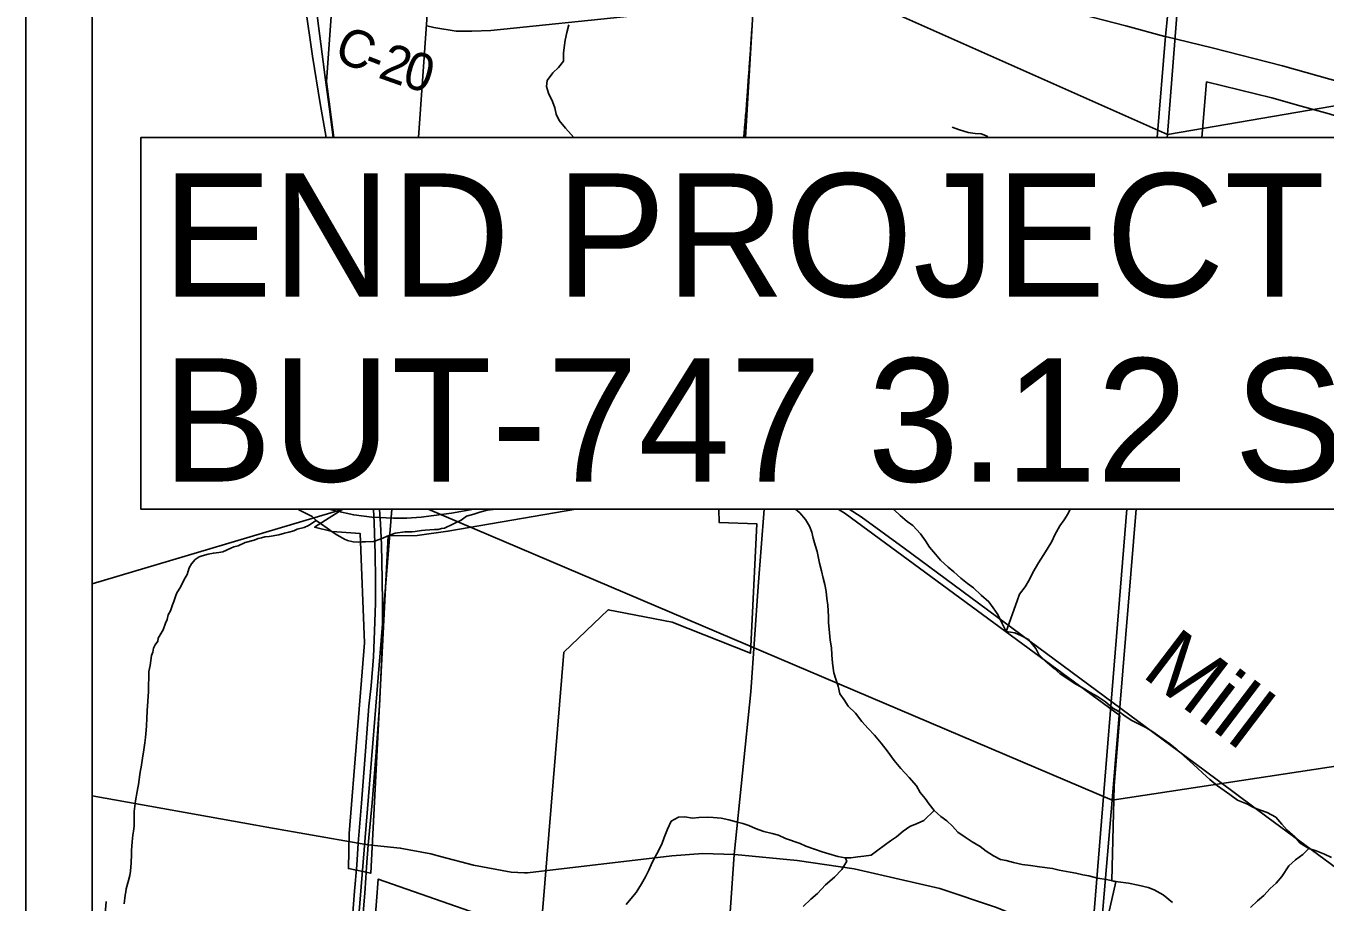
# Model space of a CAD drawing. Extents: x 0 to 34, y 0 to 22.
# Drawn here: x 2 to 3.964, y 18.207 to 19.532 of the extents above; entities that cross this region are included whole.
import ezdxf

# ---------------------------------------------------------------- set-up
doc = ezdxf.new("R2010")
doc.units = 0
for name, color, linetype in [('Default', 7, 'Continuous'), ('GM_X_City_Street', 7, 'Continuous'), ('GM_X_County_Road', 7, 'Continuous'), ('GM_X_County_Road_Text', 7, 'Continuous'), ('GM_X_Minor_River', 7, 'Continuous'), ('GM_X_Minor_River_Text', 7, 'Continuous'), ('GM_X_Rail_Line', 7, 'Continuous'), ('GM_X_Section', 7, 'Continuous'), ('GM_X_State_Route', 7, 'Continuous'), ('GM_X_Township_Road', 7, 'Continuous'), ('SH_Cut_Line', 7, 'Continuous'), ('SH_Data', 7, 'Continuous'), ('SH_Text', 7, 'Continuous')]:
    doc.layers.add(name, color=color, linetype=linetype)

msp = doc.modelspace()

# ---------------------------------------------------------------- linework, layer by layer
at = {"layer": 'Default'}
for points in [[(2.4657, 19.3633), (2.4543, 19.4479), (2.4643, 19.5889), (2.2326, 19.6977), (2.2384, 19.7007), (2.2301, 19.7049), (2.2689, 19.7927), (2.2692, 19.8013), (2.2689, 19.8136), (2.2677, 19.8229), (2.2505, 19.9535), (2.2526, 19.9723), (2.2744, 20.0988), (2.3397, 20.0939), (2.3259, 20.1979), (2.313, 20.2941), (2.2914, 20.4608), (2.2761, 20.579), (2.2821, 20.6918), (2.2391, 20.7041), (2.238, 20.7101), (2.1, 20.7213), (2.1, 19.3633)], [(2.5933, 19.3633), (2.6281, 19.856), (2.1, 19.6477), (2.1, 19.3633)], [(2.4643, 19.5889), (2.4543, 19.4479), (2.4657, 19.3633)], [(3.0852, 19.3633), (3.0855, 19.3657), (3.0858, 19.3691), (3.086, 19.3719), (3.0863, 19.3748), (3.0866, 19.3785), (3.087, 19.3827), (3.0873, 19.3864), (3.0876, 19.3898), (3.0879, 19.3932), (3.0881, 19.3963), (3.0884, 19.3997), (3.0887, 19.4031), (3.0889, 19.4053), (3.0891, 19.4076), (3.0893, 19.4104), (3.0894, 19.4127), (3.0896, 19.415), (3.0898, 19.4181), (3.09, 19.4212), (3.0902, 19.4246), (3.0905, 19.428), (3.0907, 19.4311), (3.091, 19.4351), (3.0913, 19.4388), (3.0914, 19.441), (3.0916, 19.4433), (3.0918, 19.4464), (3.0921, 19.4504), (3.0924, 19.4541), (3.0926, 19.4566), (3.0928, 19.4594), (3.093, 19.4626), (3.0932, 19.4654), (3.0934, 19.4679), (3.0936, 19.4708), (3.0938, 19.4745), (3.0941, 19.4776), (3.0943, 19.4807), (3.0946, 19.4847), (3.0948, 19.4878), (3.095, 19.4906), (3.0952, 19.4937), (3.0954, 19.496), (3.0955, 19.4985), (3.0958, 19.502), (3.096, 19.5059), (3.0963, 19.5105), (3.0966, 19.5141), (3.0968, 19.5167), (3.097, 19.5192), (3.0972, 19.5221), (3.0974, 19.5246), (3.0976, 19.5272), (3.0979, 19.5308), (3.0982, 19.5342)], [(2.1, 18.801), (2.1, 18.6881), (2.4795, 18.801)], [(2.4795, 18.801), (2.1, 18.6881), (2.1, 17.6666), (2.4678, 17.7524), (2.5533, 18.801)], [(2.1, 18.801), (2.1, 17.6674), (2.4362, 17.7466), (2.4945, 17.7428), (2.5327, 18.2417), (2.7778, 18.1558), (2.8131, 18.5849), (2.8804, 18.6491), (2.977, 18.6303), (3.0953, 18.5833), (3.1049, 18.7791), (3.0479, 18.7812), (3.0475, 18.801)], [(2.4792, 18.801), (2.4364, 18.7739), (2.4628, 18.7673), (2.5055, 18.7642), (2.512, 18.5991), (2.4887, 18.3107), (2.4876, 18.2576), (2.5212, 18.2506), (2.5475, 18.7608), (2.5913, 18.7614), (2.6379, 18.7677), (2.8315, 18.801)], [(2.8315, 18.801), (2.6379, 18.7677), (2.5913, 18.7614), (2.5475, 18.7608), (2.5212, 18.2506), (2.4876, 18.2576), (2.4887, 18.3107), (2.512, 18.5991), (2.5055, 18.7642), (2.4628, 18.7673), (2.4364, 18.7739), (2.4792, 18.801)], [(3.0475, 18.801), (3.0479, 18.7812), (3.1049, 18.7791), (3.0953, 18.5833), (2.977, 18.6303), (2.8804, 18.6491), (2.8131, 18.5849), (2.7778, 18.1558), (2.5327, 18.2417), (2.4945, 17.7428)], [(3.6366, 18.1888), (3.6479, 18.2377), (3.642, 18.2391), (3.6451, 18.3827), (3.654, 18.4891), (3.2387, 18.7947), (3.2282, 18.801)]]:
    msp.add_lwpolyline(points, dxfattribs=at)
at = {"layer": 'GM_X_City_Street'}
msp.add_line((3.0881, 19.3633), (3.1002, 19.5668), dxfattribs=at)
msp.add_lwpolyline([(2.8276, 16.5443), (2.8934, 16.7739), (2.923, 16.8761), (2.9901, 17.1121), (3.006, 17.1613), (3.0262, 17.5439), (3.0263, 17.5466), (3.0267, 17.5529), (3.0555, 18.0608), (3.0708, 18.2789), (3.0961, 18.5247), (3.1069, 18.6844), (3.1163, 18.801)], dxfattribs=at)
at = {"layer": 'GM_X_County_Road'}
for p, q in [((2.3643, 18.3202), (2.5025, 18.2962)), ((2.5025, 18.2962), (2.5176, 18.2936))]:
    msp.add_line(p, q, dxfattribs=at)
for points in [[(3.1999, 19.5773), (3.2602, 19.5828), (3.3439, 19.5909), (3.4073, 19.5947), (3.4619, 19.5839), (3.5807, 19.5533), (3.663, 19.5321), (3.722, 19.5159)], [(2.6061, 19.5319), (2.6167, 19.5295), (2.6506, 19.5239), (2.6743, 19.5237), (2.703, 19.5246), (2.918, 19.5471), (3.06, 19.5636), (3.1002, 19.5668)], [(3.722, 19.5159), (3.723, 19.5156), (3.7934, 19.4984), (3.9, 19.4714), (4.0267, 19.4358), (4.0449, 19.4335), (4.0688, 19.4339), (4.1158, 19.4408), (4.3754, 19.4815), (4.5038, 19.5025), (4.601, 19.5196), (4.6497, 19.5297), (4.6684, 19.5314)], [(2.1, 18.3678), (2.3476, 18.3232), (2.3643, 18.3202)], [(2.5176, 18.2936), (2.5659, 18.2886), (2.612, 18.28), (2.6265, 18.2762)], [(2.6265, 18.2762), (2.6768, 18.2629), (2.7335, 18.2524), (2.7535, 18.2513)], [(2.7535, 18.2513), (2.7585, 18.2511), (2.9767, 18.2769), (3.0232, 18.2806), (3.0708, 18.2789), (3.0718, 18.2788)], [(3.0718, 18.2788), (3.1658, 18.2699), (3.2524, 18.2573), (3.3817, 18.2277), (3.4672, 18.1987), (3.5902, 18.1482), (3.6107, 18.1365), (3.6157, 18.1336), (3.627, 18.1271)]]:
    msp.add_lwpolyline(points, dxfattribs=at)
at = {"layer": 'GM_X_Minor_River'}
for points in [[(2.815, 19.5103), (2.8176, 19.5216), (2.8206, 19.5333)], [(2.8282, 19.3633), (2.8241, 19.3674), (2.8156, 19.3772), (2.8061, 19.3889), (2.8018, 19.3981), (2.7998, 19.4077), (2.7959, 19.4177), (2.7902, 19.4301), (2.7871, 19.4404), (2.7881, 19.4495), (2.7964, 19.461), (2.8054, 19.4691), (2.8125, 19.4784), (2.8129, 19.4906), (2.8135, 19.4993), (2.815, 19.5103)], [(3.4555, 19.3633), (3.4531, 19.3649), (3.4444, 19.3686), (3.4349, 19.3693), (3.4243, 19.3708), (3.41, 19.375), (3.4003, 19.3787)], [(2.6329, 18.7722), (2.6283, 18.772), (2.623, 18.7706), (2.6176, 18.7703), (2.6108, 18.7701), (2.6035, 18.7696), (2.5982, 18.7689), (2.5882, 18.7673), (2.5837, 18.767), (2.573, 18.7669), (2.5581, 18.7646), (2.5485, 18.7615), (2.537, 18.7564), (2.5255, 18.7522), (2.5133, 18.7517), (2.5083, 18.7515), (2.5034, 18.7512), (2.4946, 18.7518), (2.4859, 18.7539), (2.4814, 18.756), (2.4747, 18.7596), (2.4698, 18.7623), (2.4646, 18.7659), (2.4552, 18.7722), (2.4466, 18.7782), (2.4388, 18.7841), (2.4329, 18.7899), (2.4235, 18.7947), (2.4156, 18.7987), (2.4108, 18.801)], [(2.7172, 18.801), (2.7162, 18.801), (2.7063, 18.8005), (2.6971, 18.7996), (2.686, 18.7966), (2.6772, 18.7934), (2.6661, 18.7903), (2.6579, 18.7843), (2.6329, 18.7722)], [(3.7333, 18.2065), (3.7195, 18.218), (3.7057, 18.2256), (3.6967, 18.2289), (3.6816, 18.2324), (3.6668, 18.2356), (3.6513, 18.2379), (3.6426, 18.2393), (3.6339, 18.2411), (3.6203, 18.2434), (3.6071, 18.2469), (3.5977, 18.2483), (3.5875, 18.2509), (3.5788, 18.2523), (3.5621, 18.2555), (3.5519, 18.2577), (3.5323, 18.2602), (3.5186, 18.2621), (3.5061, 18.264), (3.4929, 18.2671), (3.482, 18.2697), (3.4733, 18.2715), (3.4628, 18.2771), (3.4516, 18.2839), (3.4427, 18.2911), (3.4304, 18.2979), (3.4199, 18.3051), (3.4091, 18.313), (3.4007, 18.3216), (3.3922, 18.3299), (3.3832, 18.3362), (3.3732, 18.3453), (3.3655, 18.355), (3.3593, 18.3639), (3.352, 18.3729), (3.3462, 18.383), (3.3352, 18.3955), (3.3227, 18.4091), (3.3127, 18.4212), (3.3021, 18.4356), (3.293, 18.4473), (3.2827, 18.4594), (3.2735, 18.4696), (3.2639, 18.4801), (3.2544, 18.4926), (3.2433, 18.5032), (3.2371, 18.5129), (3.2306, 18.5218), (3.2279, 18.5337), (3.2244, 18.544), (3.2216, 18.5536), (3.2194, 18.5681), (3.2186, 18.5807), (3.2178, 18.5914), (3.2159, 18.6028), (3.2151, 18.6143), (3.2136, 18.6299), (3.2135, 18.639), (3.2125, 18.6562), (3.2109, 18.6661), (3.2097, 18.6764), (3.2077, 18.6871), (3.2053, 18.6967), (3.203, 18.7078), (3.1999, 18.7196), (3.1962, 18.7369), (3.1931, 18.7468), (3.1904, 18.7572), (3.188, 18.7664), (3.1848, 18.7756), (3.1787, 18.7857), (3.1702, 18.7954), (3.1634, 18.801)], [(3.5637, 18.5523), (3.5548, 18.5602), (3.5411, 18.5716), (3.5315, 18.5814), (3.5268, 18.5903), (3.5158, 18.6039), (3.5053, 18.6096), (3.4952, 18.6141), (3.4819, 18.6164), (3.4758, 18.628), (3.4694, 18.6418), (3.4625, 18.6519), (3.4559, 18.6609), (3.4444, 18.6711), (3.4326, 18.6821), (3.4236, 18.6889), (3.4136, 18.6968), (3.4029, 18.7066), (3.3943, 18.7133), (3.3829, 18.7239), (3.3751, 18.7329), (3.3663, 18.7438), (3.3598, 18.7532), (3.3525, 18.764), (3.3411, 18.7762), (3.3325, 18.7825), (3.3218, 18.7916), (3.3129, 18.8002), (3.312, 18.801)], [(3.4819, 18.6164), (3.4985, 18.6626), (3.5022, 18.6724), (3.5105, 18.6839), (3.5173, 18.6947), (3.5222, 18.7052), (3.531, 18.7198), (3.5381, 18.731), (3.5438, 18.7407), (3.5513, 18.7522), (3.5558, 18.7624), (3.563, 18.7758), (3.5698, 18.7851), (3.5758, 18.7948), (3.5787, 18.801)], [(2.4388, 18.7841), (2.4272, 18.7764), (2.4206, 18.7735), (2.4099, 18.7707), (2.4049, 18.7686), (2.3972, 18.7661), (2.3911, 18.7648), (2.3823, 18.7623), (2.3678, 18.76), (2.3609, 18.7591), (2.3563, 18.758), (2.351, 18.7567), (2.3448, 18.7542), (2.3314, 18.7507), (2.321, 18.7456), (2.3145, 18.7443), (2.3099, 18.7421), (2.2975, 18.7367), (2.2914, 18.7357), (2.2834, 18.7348), (2.2754, 18.7331), (2.2666, 18.7307), (2.2616, 18.7289), (2.2558, 18.7249), (2.2503, 18.7185), (2.2467, 18.7125), (2.2454, 18.7076), (2.2438, 18.7024), (2.2394, 18.6949), (2.2334, 18.6832), (2.2282, 18.6746), (2.2261, 18.6693), (2.2233, 18.6614), (2.2216, 18.6565), (2.2187, 18.6475), (2.2151, 18.6411), (2.2134, 18.6343), (2.211, 18.6286), (2.2073, 18.6185), (2.2001, 18.6061), (2.1992, 18.6015), (2.1953, 18.5959), (2.1929, 18.591), (2.1916, 18.585), (2.1899, 18.5797), (2.1886, 18.5721), (2.1876, 18.5649), (2.1859, 18.5555), (2.1851, 18.5254), (2.1843, 18.5106), (2.1831, 18.4962), (2.1828, 18.4844), (2.1822, 18.4734), (2.1816, 18.4669), (2.1809, 18.4559), (2.1796, 18.4476), (2.1782, 18.4373), (2.1763, 18.4248), (2.174, 18.4112), (2.1732, 18.4067), (2.1722, 18.3998), (2.1703, 18.3847), (2.169, 18.3798), (2.1681, 18.3741), (2.1655, 18.3601), (2.1635, 18.3438), (2.1634, 18.3388), (2.1636, 18.3327), (2.1637, 18.3217), (2.1624, 18.3145), (2.1614, 18.3084), (2.1604, 18.2982), (2.1597, 18.2849), (2.1595, 18.2792), (2.1588, 18.2663), (2.1581, 18.2537), (2.1572, 18.2473), (2.1551, 18.2397), (2.1517, 18.2273), (2.1512, 18.2223), (2.1499, 18.2174), (2.1484, 18.2045)], [(3.974, 18.2744), (3.9631, 18.2797), (3.9507, 18.2843), (3.9398, 18.288), (3.9267, 18.296), (3.9183, 18.3058), (3.9071, 18.3156), (3.8987, 18.325), (3.8895, 18.3356), (3.8764, 18.3424), (3.8666, 18.3461), (3.8561, 18.3499), (3.8467, 18.3551), (3.8317, 18.3613), (3.8202, 18.3696), (3.8116, 18.3756), (3.8015, 18.3827), (3.7897, 18.3926), (3.7793, 18.402), (3.7708, 18.4099), (3.7601, 18.4197), (3.7508, 18.4284), (3.7404, 18.437), (3.7293, 18.4465), (3.7144, 18.4568), (3.7036, 18.4644), (3.6932, 18.4708), (3.6812, 18.4772), (3.6722, 18.4817), (3.6621, 18.4881), (3.6524, 18.4952), (3.6435, 18.5001), (3.632, 18.5099), (3.62, 18.5179), (3.61, 18.5235), (3.5958, 18.5319), (3.5864, 18.5368), (3.5767, 18.5435), (3.5637, 18.5523)], [(3.3732, 18.3453), (3.3576, 18.3302), (3.3472, 18.3259), (3.3364, 18.3213), (3.3263, 18.3144), (3.3162, 18.3056), (3.3069, 18.2994), (3.2882, 18.2855), (3.2781, 18.2782), (3.2667, 18.2763), (3.2575, 18.2754), (3.2472, 18.2738), (3.2385, 18.2737), (3.2275, 18.276), (3.214, 18.2802), (3.2038, 18.2832), (3.1921, 18.2869), (3.1789, 18.2915), (3.1703, 18.2956), (3.1485, 18.3031), (3.1376, 18.308), (3.1282, 18.3106), (3.1154, 18.3136), (3.103, 18.3185), (3.0928, 18.3227), (3.0838, 18.326), (3.074, 18.3286), (3.0627, 18.3316), (3.0513, 18.3338), (3.0388, 18.335), (3.0297, 18.3352), (3.0175, 18.3348), (3.008, 18.334), (2.9963, 18.3359), (2.9864, 18.3354), (2.9756, 18.3293), (2.9699, 18.3173), (2.9649, 18.3045), (2.962, 18.2959), (2.9564, 18.2846), (2.9512, 18.2753), (2.9467, 18.2667), (2.9418, 18.2551), (2.9366, 18.245), (2.9306, 18.2345), (2.9226, 18.2214), (2.9147, 18.2122), (2.9076, 18.2033)], [(3.9398, 18.288), (3.9308, 18.2792), (3.9195, 18.2708), (3.9094, 18.262), (3.8986, 18.2456), (3.89, 18.2356), (3.881, 18.2275), (3.8715, 18.2171), (3.8622, 18.2087), (3.8516, 18.1987)], [(3.2385, 18.2737), (3.241, 18.2687), (3.2335, 18.2564), (3.2222, 18.2445), (3.2086, 18.2331), (3.1965, 18.2201), (3.1868, 18.2116), (3.1751, 18.2005)]]:
    msp.add_lwpolyline(points, dxfattribs=at)
at = {"layer": 'GM_X_Rail_Line'}
for points in [[(2.6771, 18.801), (2.6434, 18.7952), (2.6169, 18.7914), (2.5973, 18.7888), (2.5758, 18.7873), (2.5558, 18.7873), (2.5231, 18.7891), (2.4955, 18.7924), (2.4678, 18.7985), (2.4579, 18.801)], [(4.3528, 17.9844), (3.8782, 18.3346), (3.7815, 18.4067), (3.5682, 18.5641), (3.3277, 18.7422), (3.2626, 18.7894), (3.2446, 18.801)], [(2.121, 18.1403), (2.1193, 18.1508), (2.118, 18.1712), (2.121, 18.2077)]]:
    msp.add_lwpolyline(points, dxfattribs=at)
at = {"layer": 'GM_X_Section'}
for points in [[(2.7095, 20.8874), (2.8405, 20.8285), (3.806, 20.3918), (3.7257, 19.3674), (2.6281, 19.856)], [(4.818, 20.3144), (4.7613, 19.5448), (3.7257, 19.3674), (3.806, 20.3918)], [(4.6831, 18.5192), (4.5906, 17.4897), (3.5572, 17.3639), (3.6423, 18.3609)]]:
    msp.add_lwpolyline(points, close=True, dxfattribs=at)
for points in [[(2.5933, 19.3633), (2.6281, 19.856), (3.7257, 19.3674), (3.7253, 19.3633)], [(3.7253, 19.3633), (3.7257, 19.3674), (4.7613, 19.5448), (4.6831, 18.5192), (3.6423, 18.3609), (3.6787, 18.801)], [(2.6081, 18.801), (3.6423, 18.3609), (3.5572, 17.3639), (2.4678, 17.7524), (2.5533, 18.801)], [(3.6787, 18.801), (3.6423, 18.3609), (2.6081, 18.801)]]:
    msp.add_lwpolyline(points, dxfattribs=at)
at = {"layer": 'GM_X_State_Route'}
for points in [[(2.4541, 19.3633), (2.4449, 19.4144), (2.4331, 19.4862), (2.4223, 19.5631), (2.416, 19.6111)], [(2.4525, 19.4538), (2.4492, 19.4777), (2.4393, 19.5551), (2.433, 19.603), (2.4316, 19.6129)], [(2.4647, 19.3633), (2.459, 19.4059), (2.4525, 19.4538)], [(2.5025, 18.2962), (2.5071, 18.3566), (2.5131, 18.4352), (2.5182, 18.5031), (2.5219, 18.5341), (2.5252, 18.5779), (2.5267, 18.6165), (2.5284, 18.6597), (2.5284, 18.6951), (2.5282, 18.7334), (2.5265, 18.7803), (2.5254, 18.801)], [(2.5139, 18.2436), (2.5151, 18.2597), (2.5176, 18.2936), (2.5233, 18.3573), (2.5289, 18.4273), (2.5345, 18.504), (2.5367, 18.5462), (2.5388, 18.604), (2.5391, 18.6586), (2.5383, 18.6954), (2.5374, 18.747), (2.5362, 18.779), (2.5347, 18.801)], [(2.4653, 17.7473), (2.4678, 17.773), (2.473, 17.8306), (2.4772, 17.8778), (2.4811, 17.9282), (2.4838, 17.9759), (2.4853, 18.0171), (2.4877, 18.0978), (2.4912, 18.1516), (2.4969, 18.2236), (2.5, 18.2627), (2.5025, 18.2962)], [(2.4925, 17.9643), (2.4956, 18.0091), (2.5018, 18.089), (2.5063, 18.1486), (2.5121, 18.2206), (2.5139, 18.2436)]]:
    msp.add_lwpolyline(points, dxfattribs=at)
at = {"layer": 'GM_X_Township_Road'}
for p, q in [((3.7776, 19.3633), (3.7849, 19.4474)), ((3.8463, 19.3633), (3.8463, 19.3635))]:
    msp.add_line(p, q, dxfattribs=at)
for points in [[(3.7103, 19.3633), (3.7228, 19.5162), (3.8114, 20.3941), (3.8135, 20.4321), (3.8191, 20.5134), (3.8272, 20.6073), (3.8479, 20.9), (2.1, 20.9), (2.1, 18.801)], [(4.0283, 20.3778), (3.9475, 20.3839), (3.8114, 20.3941), (3.7228, 19.5162), (3.7103, 19.3633)], [(3.7849, 19.4474), (3.8838, 19.4231), (3.9279, 19.4102), (3.9703, 19.3989), (3.9814, 19.3954), (3.9894, 19.3909), (3.9973, 19.3844), (4.0031, 19.3765), (4.0077, 19.3677)], [(2.1, 18.801), (2.1, 15.6427), (2.3082, 15.6745), (2.4145, 15.6427), (2.5606, 15.599), (3.3455, 15.3733), (3.3845, 15.362), (3.4311, 15.9332), (3.4604, 16.2167), (3.4676, 16.3592), (3.5285, 17.1302), (3.548, 17.3706), (3.5984, 17.9897), (3.6087, 18.1157), (3.6104, 18.137), (3.6645, 18.801)], [(3.6645, 18.801), (3.6104, 18.137)]]:
    msp.add_lwpolyline(points, dxfattribs=at)
at = {"layer": 'SH_Cut_Line'}
for points in [[(8.9, 14.8595), (8.9, 20.9), (2.1, 20.9), (2.1, 19.3633)], [(2.1, 18.801), (2.1, 15.6427)]]:
    msp.add_lwpolyline(points, dxfattribs=at)
at = {"layer": 'SH_Data'}
for p, q in [((2, 21), (2, 14)), ((2.1, 20.9), (2.1, 14.1))]:
    msp.add_line(p, q, dxfattribs=at)
at = {"layer": 'SH_Text'}
msp.add_lwpolyline([(4.4279, 19.3633), (2.1739, 19.3633), (2.1739, 18.801), (4.4279, 18.801)], close=True, dxfattribs=at)

# ---------------------------------------------------------------- texts
at = {"layer": 'GM_X_County_Road_Text'}
for s, rotation, p in [('C', 337.207, (2.463, 19.4819)), ('2', 340.4622, (2.5305, 19.4542)), ('-', 338.3983, (2.5069, 19.4635)), ('0', 343.8109, (2.5667, 19.4414))]:
    msp.add_text(s, height=0.0568, rotation=rotation, dxfattribs=at).set_placement(p)
at = {"layer": 'GM_X_Minor_River_Text'}
msp.add_text('Mill', height=0.09469, rotation=322.7659, dxfattribs=at).set_placement((3.6846, 18.5499))
at = {"layer": 'SH_Text'}
for s, p in [('END PROJECT', (2.206, 19.1224)), ('BUT-747 3.12 SLM', (2.206, 18.8429))]:
    msp.add_text(s, height=0.18634, dxfattribs=at).set_placement(p)

doc.saveas('drawing.dxf')
